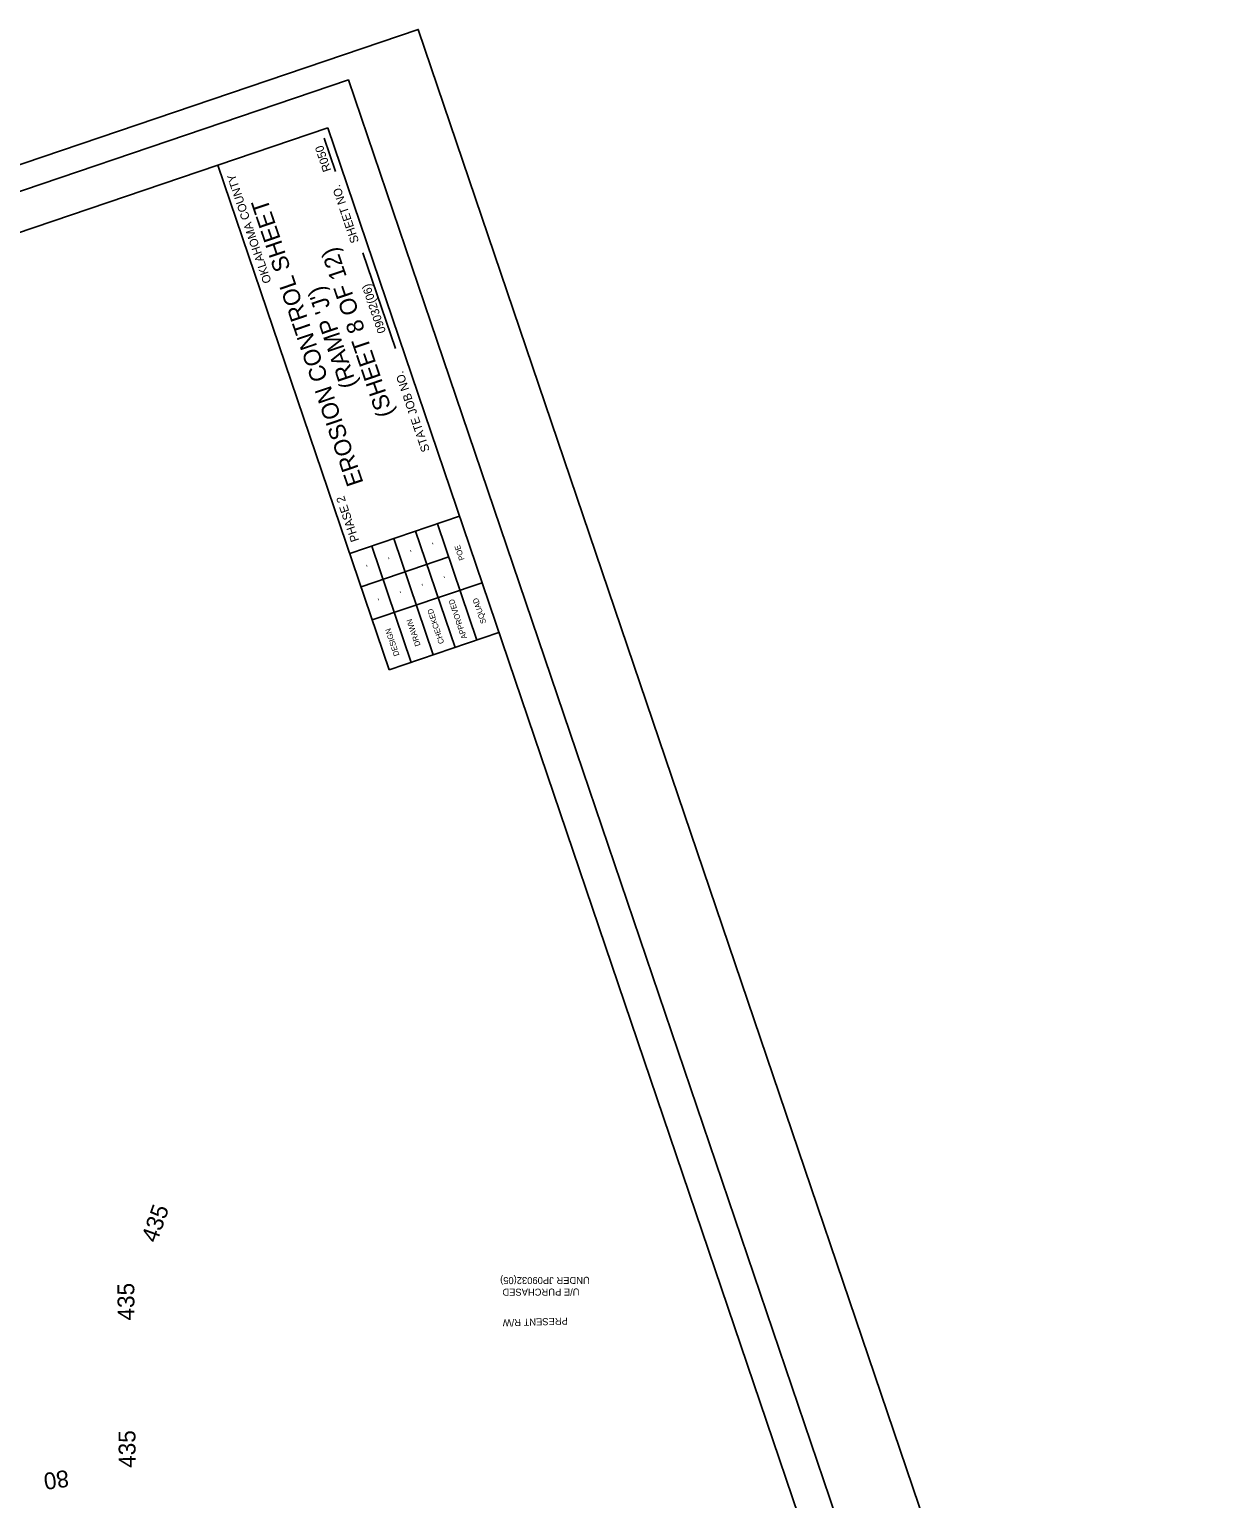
# Model space of a CAD drawing. Extents: x 2150575 to 2152290, y 141864 to 143954.
# Drawn here: x 2151434 to 2152290, y 142907 to 143954 of the extents above; entities that cross this region are included whole.
import ezdxf

# ---------------------------------------------------------------- set-up
doc = ezdxf.new("R2010")
doc.units = 0
for name, color, linetype in [('BASELINE', 7, 'Continuous'), ('PR_ABUT_PH3', 7, 'Continuous'), ('PR_Align_2_Sta', 7, 'Continuous'), ('PR_Align_Ramp_A', 7, 'Continuous'), ('PR_Align_Ramp_F_Txt', 7, 'Continuous'), ('PR_Align_Ramp_H_Sta', 7, 'Continuous'), ('PR_Align_Ramp_I_Sta', 7, 'Continuous'), ('PR_Align_Ramp_J_Sta', 7, 'Continuous'), ('PR_Bridge_Pier_PH4', 7, 'Continuous'), ('PR_Road_Concrete', 7, 'Continuous'), ('SHT_Standard_Sheet_Txt', 7, 'Continuous')]:
    doc.layers.add(name, color=color, linetype=linetype)

msp = doc.modelspace()

# ---------------------------------------------------------------- linework, layer by layer
at = {"layer": 'BASELINE'}
msp.add_lwpolyline([(2151166, 141954.5), (2150619.8, 143564.3), (2151661.5, 143917.7), (2152207.7, 142307.8)], close=True, dxfattribs=at)
at = {"layer": 'PR_ABUT_PH3'}
msp.add_lwpolyline([(2151153.2, 141863.7), (2150574.9, 143568.3), (2151711.3, 143953.8), (2152289.6, 142249.2)], close=True, dxfattribs=at)
at = {"layer": 'PR_Bridge_Pier_PH4'}
for p, q in [((2151652.2, 143852.5), (2151644.1, 143876.3)), ((2151695, 143726.4), (2151671.8, 143794.6)), ((2151733, 143577.7), (2151670.5, 143556.5)), ((2151756.7, 143559.3), (2151678.5, 143532.8))]:
    msp.add_line(p, q, dxfattribs=at)
for points in [[(2151725, 143601.4), (2151753.1, 143518.5)], [(2151693.8, 143590.8), (2151721.9, 143507.9)], [(2151709.4, 143596.1), (2151737.5, 143513.2)], [(2151678.1, 143585.5), (2151706.3, 143502.6)]]:
    msp.add_lwpolyline(points, dxfattribs=at)
at = {"layer": 'PR_Road_Concrete'}
for p, q in [((2151690.6, 143497.3), (2151568.5, 143857.1)), ((2151740.6, 143606.7), (2151662.5, 143580.1)), ((2151768.8, 143523.8), (2151690.6, 143497.3))]:
    msp.add_line(p, q, dxfattribs=at)
msp.add_lwpolyline([(2151646.7, 143883.7), (2152152.7, 142392.1), (2151158.3, 142054.8), (2150652.3, 143546.3)], close=True, dxfattribs=at)

# ---------------------------------------------------------------- texts
at = {"layer": 'PR_Align_2_Sta'}
msp.add_text('435', height=12, rotation=90.4098, dxfattribs=at).set_placement((2151509.8, 142928.5))
at = {"layer": 'PR_Align_Ramp_A'}
msp.add_text('PRESENT R/W', height=5, rotation=181.6818, dxfattribs=at).set_placement((2151817.8, 143035.6))
at = {"layer": 'PR_Align_Ramp_F_Txt'}
for s, p in [('UNDER JP09032(05)', (2151833.5, 143064.6)), ('U/E PURCHASED', (2151826.2, 143056.3))]:
    msp.add_text(s, height=5, rotation=180.2053, dxfattribs=at).set_placement(p)
at = {"layer": 'PR_Align_Ramp_H_Sta'}
msp.add_text('435', height=12, rotation=70.3098, dxfattribs=at).set_placement((2151524.8, 143088.2))
at = {"layer": 'PR_Align_Ramp_I_Sta'}
msp.add_text('435', height=12, rotation=90.4098, dxfattribs=at).set_placement((2151509, 143033.5))
at = {"layer": 'PR_Align_Ramp_J_Sta'}
msp.add_text('80', height=12, rotation=187.8425, dxfattribs=at).set_placement((2151461.3, 142927))
at = {"layer": 'SHT_Standard_Sheet_Txt'}
for s, height, p in [('R050', 6, (2151649.3, 143853.4)), ('OKLAHOMA COUNTY', 6, (2151606.7, 143773.9)), ('SHEET NO. ', 6, (2151669.1, 143802.6)), ('EROSION CONTROL SHEET', 12, (2151672.3, 143630.6)), ('(SHEET 8 OF 12)', 12, (2151693.7, 143679.6)), ("(RAMP 'J')", 12, (2151667.7, 143700.2)), ('09032(06)', 6, (2151688.3, 143738.3)), ('STATE JOB NO.', 6, (2151719.6, 143653.7)), ('PHASE 2', 6, (2151669.2, 143589.6)), ('-', 4, (2151707.7, 143581.7)), ('-', 4, (2151723.3, 143587)), ('POE', 4, (2151744.4, 143576)), ('-', 4, (2151676.4, 143571.1)), ('-', 4, (2151692, 143576.4)), ('-', 4, (2151715.8, 143557.6)), ('-', 4, (2151731.5, 143562.9)), ('-', 4, (2151684.6, 143547)), ('-', 4, (2151700.2, 143552.3)), ('SQUAD', 4, (2151759.8, 143530.9)), ('CHECKED', 4, (2151729.8, 143516.5)), ('APPROVED', 4, (2151746.1, 143520)), ('DRAWN', 4, (2151713, 143514.8)), ('DESIGN', 4, (2151697.9, 143507.8))]:
    msp.add_text(s, height=height, rotation=108.7393, dxfattribs=at).set_placement(p)

doc.saveas('drawing.dxf')
